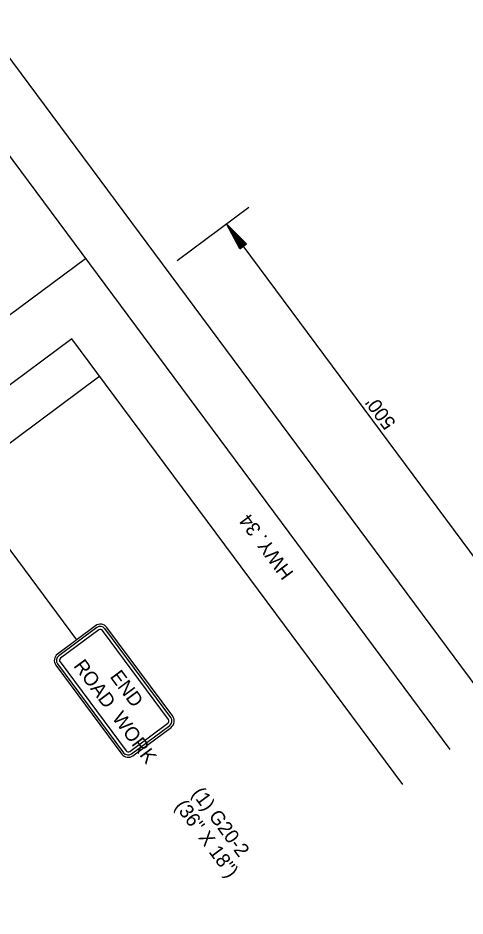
# Model space of a CAD drawing. Extents: x 998982 to 1000630, y 1875366 to 1876934.
# Drawn here: x 1000152.3 to 1000343, y 1876021.6 to 1876404.6 of the extents above; entities that cross this region are included whole.
import ezdxf

# ---------------------------------------------------------------- set-up
doc = ezdxf.new("R2010")
doc.units = 0
for name, color, linetype in [('P_TC_Signs_Temporary', 7, 'Continuous'), ('R_Border Prem', 7, 'Continuous'), ('R_Draft', 7, 'Continuous')]:
    doc.layers.add(name, color=color, linetype=linetype)

msp = doc.modelspace()

# ---------------------------------------------------------------- linework, layer by layer
at = {"layer": 'P_TC_Signs_Temporary'}
for p, q in [((1000185.39, 1876145.39), (1000169.13, 1876133.32)), ((1000185.95, 1876144.64), (1000169.69, 1876132.57)), ((1000186.73, 1876143.59), (1000170.47, 1876131.52)), ((1000217.53, 1876106.2), (1000189.36, 1876144.14)), ((1000218.28, 1876106.76), (1000190.11, 1876144.7)), ((1000216.47, 1876105.42), (1000188.3, 1876143.36)), ((1000168.43, 1876128.6), (1000196.6, 1876090.66)), ((1000169.19, 1876129.16), (1000197.35, 1876091.22)), ((1000170.24, 1876129.94), (1000198.41, 1876092.01)), ((1000199.98, 1876091.77), (1000216.24, 1876103.85)), ((1000200.76, 1876090.72), (1000217.02, 1876102.79)), ((1000201.32, 1876089.97), (1000217.58, 1876102.04))]:
    msp.add_line(p, q, dxfattribs=at)
for centre, radius, start, end in [((1000187.4, 1876142.68), 3.38, 36.5953, 126.5953), ((1000187.4, 1876142.68), 2.44, 36.5953, 126.5953), ((1000187.4, 1876142.68), 1.13, 36.5953, 126.5953), ((1000171.14, 1876130.61), 3.38, 126.5953, 216.5953), ((1000171.14, 1876130.61), 2.44, 126.5953, 216.5953), ((1000171.14, 1876130.61), 1.13, 126.5953, 216.5953), ((1000215.57, 1876104.75), 1.13, 306.5953, 36.5953), ((1000215.57, 1876104.75), 2.44, 306.5953, 36.5953), ((1000215.57, 1876104.75), 3.38, 306.5953, 36.5953), ((1000199.31, 1876092.68), 3.38, 216.5953, 306.5953), ((1000199.31, 1876092.68), 2.44, 216.5953, 306.5953), ((1000199.31, 1876092.68), 1.13, 216.5953, 306.5953)]:
    msp.add_arc(centre, radius, start, end, dxfattribs=at)
at = {"layer": 'R_Draft'}
for p, q in [((1000356.62, 1876107.48), (1000045.75, 1876526.13)), ((1000025.68, 1876511.22), (1000336.54, 1876092.57)), ((1000250.71, 1876323.75), (1000220.18, 1876301.08)), ((1000241.26, 1876316.75), (1000360.5, 1876156.17)), ((1000246.96, 1876306.07), (1000241.26, 1876316.75)), ((1000249.84, 1876308.21), (1000241.26, 1876316.75)), ((1000247.2, 1876306.25), (1000242.46, 1876315.14)), ((1000249.6, 1876308.03), (1000242.46, 1876315.14)), ((1000249.36, 1876307.85), (1000243.68, 1876313.49)), ((1000247.44, 1876306.43), (1000243.68, 1876313.49)), ((1000247.68, 1876306.61), (1000244.87, 1876311.89)), ((1000249.12, 1876307.67), (1000244.87, 1876311.89)), ((1000248.87, 1876307.49), (1000246.08, 1876310.26)), ((1000247.93, 1876306.79), (1000246.08, 1876310.26)), ((1000246.96, 1876306.07), (1000249.84, 1876308.21)), ((1000248.63, 1876307.31), (1000247.27, 1876308.66)), ((1000248.17, 1876306.97), (1000247.27, 1876308.66)), ((1000181.11, 1876301.9), (999851.04, 1876056.81)), ((1000175.31, 1876267.77), (999865.31, 1876037.59)), ((1000316.47, 1876077.67), (1000175.31, 1876267.77)), ((1000187.2, 1876251.76), (999877.2, 1876021.57)), ((1000141.45, 1876187.58), (1000177.26, 1876139.36))]:
    msp.add_line(p, q, dxfattribs=at)

# ---------------------------------------------------------------- texts
at = {"layer": 'P_TC_Signs_Temporary'}
for s, p in [('ROAD  WORK', (1000175.73, 1876128.21)), ('END', (1000191.27, 1876123.64))]:
    msp.add_text(s, height=6, rotation=306.5953, dxfattribs=at).set_placement(p)
at = {"layer": 'R_Border Prem'}
for s, rotation, p in [("500'", 126.5953, (1000313.78, 1876231.92)), ('HWY. 34', 126.5953, (1000270.14, 1876167.9)), ('(1) G20-2', 306.5953, (1000226.19, 1876073.78)), ('(36" X 18")', 306.5953, (1000218.97, 1876068.42))]:
    msp.add_text(s, height=6, rotation=rotation, dxfattribs=at).set_placement(p)

doc.saveas('drawing.dxf')
